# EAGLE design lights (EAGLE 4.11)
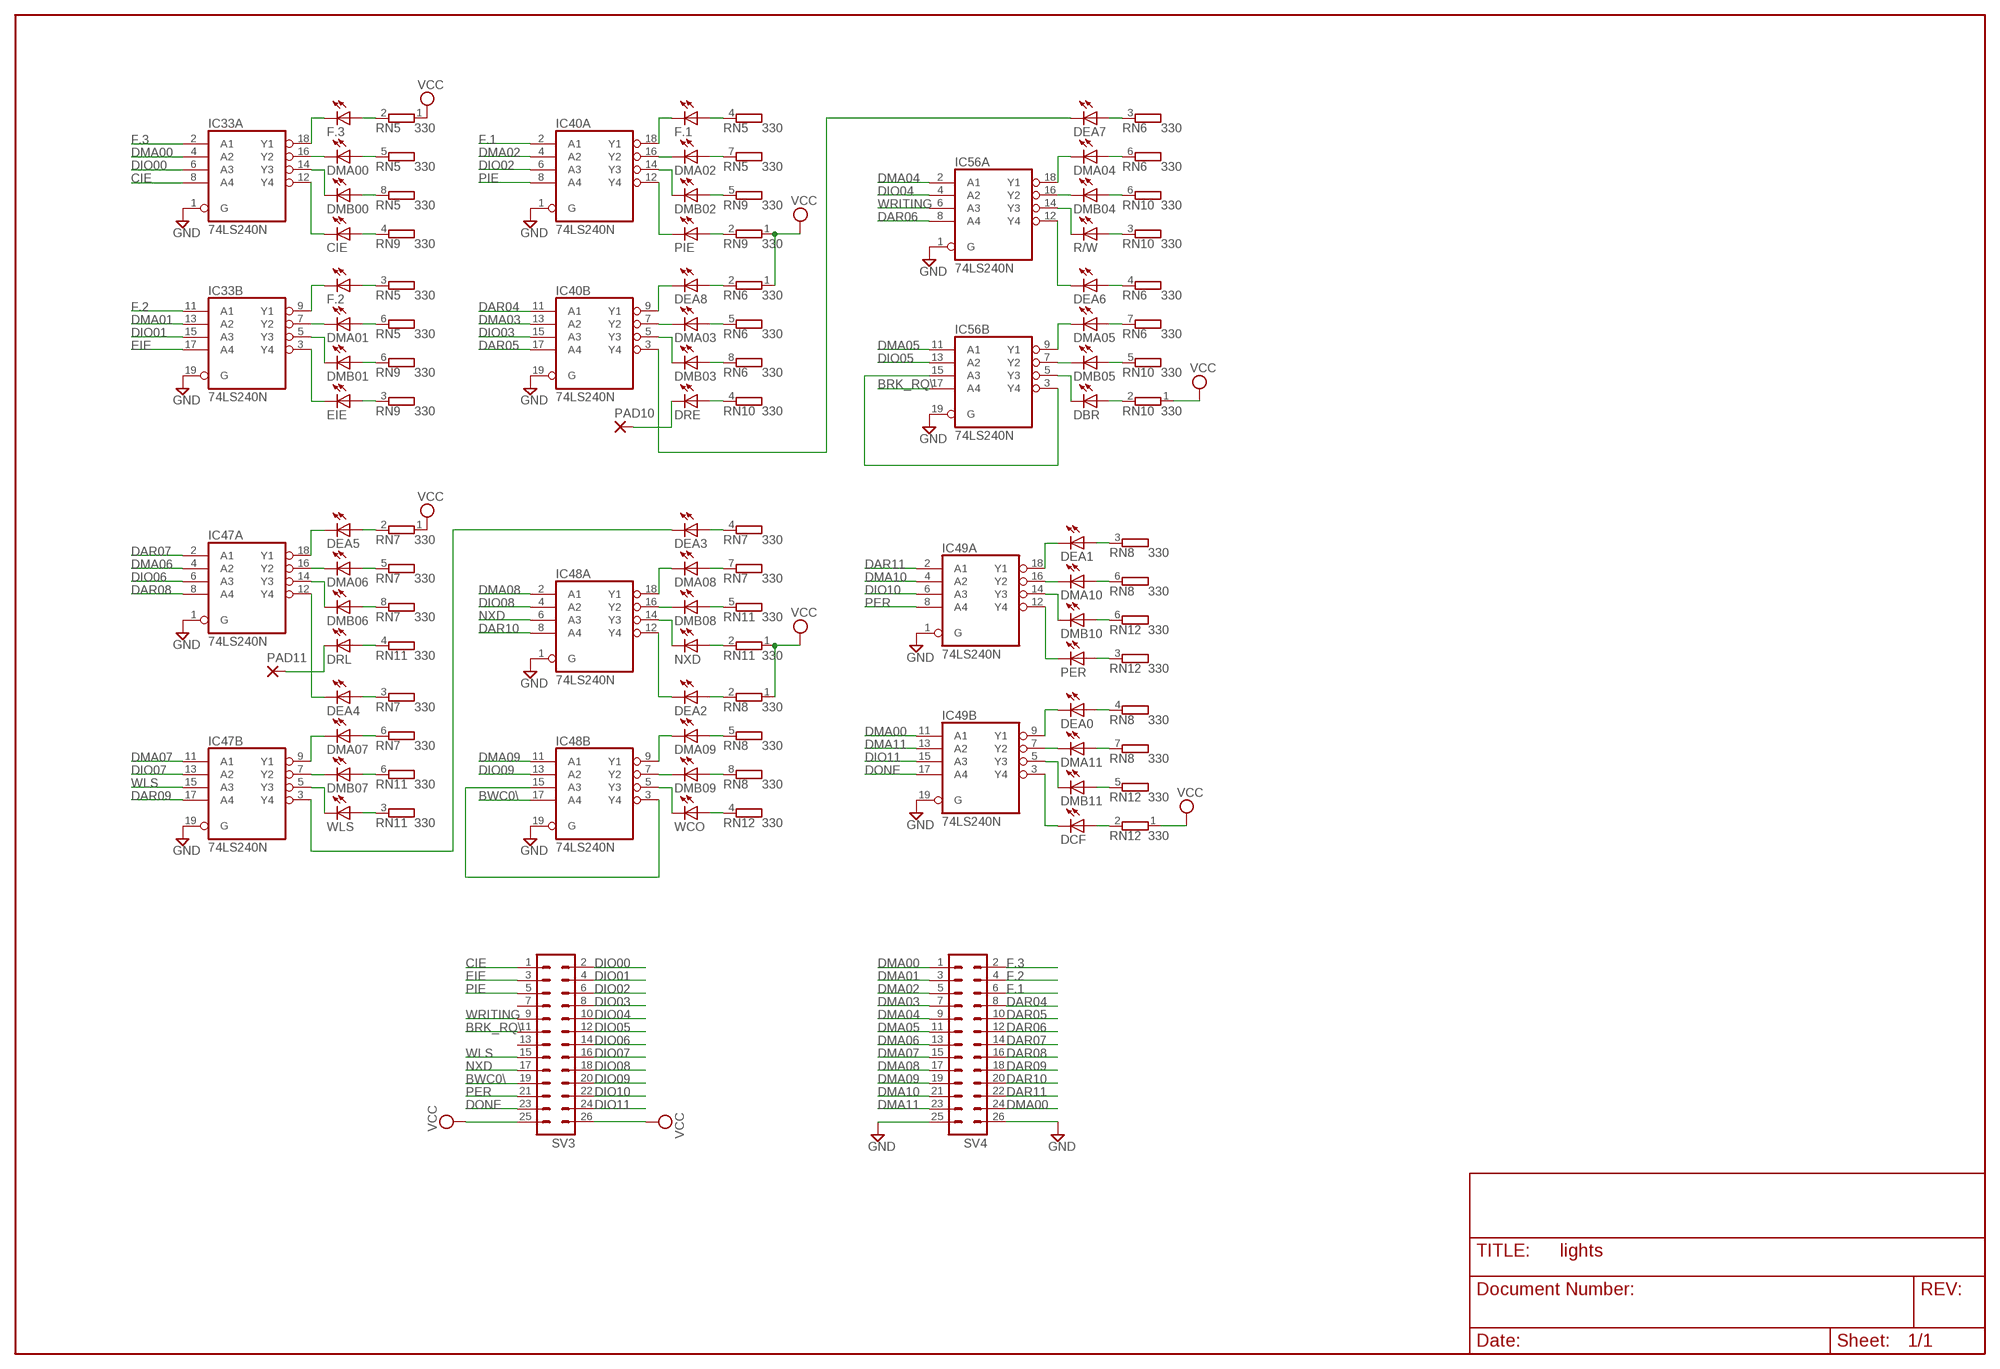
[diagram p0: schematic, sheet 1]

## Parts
CIE  LED5MM  [LED5MM]
DBR  LED5MM  [LED5MM]
DCF  LED5MM  [LED5MM]
DEA0  LED5MM  [LED5MM]
DEA1  LED5MM  [LED5MM]
DEA2  LED5MM  [LED5MM]
DEA3  LED5MM  [LED5MM]
DEA4  LED5MM  [LED5MM]
DEA5  LED5MM  [LED5MM]
DEA6  LED5MM  [LED5MM]
DEA7  LED5MM  [LED5MM]
DEA8  LED5MM  [LED5MM]
DMA00  LED5MM  [LED5MM]
DMA01  LED5MM  [LED5MM]
DMA02  LED5MM  [LED5MM]
DMA03  LED5MM  [LED5MM]
DMA04  LED5MM  [LED5MM]
DMA05  LED5MM  [LED5MM]
DMA06  LED5MM  [LED5MM]
DMA07  LED5MM  [LED5MM]
DMA08  LED5MM  [LED5MM]
DMA09  LED5MM  [LED5MM]
DMA10  LED5MM  [LED5MM]
DMA11  LED5MM  [LED5MM]
DMB00  LED5MM  [LED5MM]
DMB01  LED5MM  [LED5MM]
DMB02  LED5MM  [LED5MM]
DMB03  LED5MM  [LED5MM]
DMB04  LED5MM  [LED5MM]
DMB05  LED5MM  [LED5MM]
DMB06  LED5MM  [LED5MM]
DMB07  LED5MM  [LED5MM]
DMB08  LED5MM  [LED5MM]
DMB09  LED5MM  [LED5MM]
DMB10  LED5MM  [LED5MM]
DMB11  LED5MM  [LED5MM]
DRE  LED5MM  [LED5MM]
DRL  LED5MM  [LED5MM]
EIE  LED5MM  [LED5MM]
F.1  LED5MM  [LED5MM]
F.2  LED5MM  [LED5MM]
F.3  LED5MM  [LED5MM]
IC33  74LS240N  [DIL20]
IC40  74LS240N  [DIL20]
IC47  74LS240N  [DIL20]
IC48  74LS240N  [DIL20]
IC49  74LS240N  [DIL20]
IC56  74LS240N  [DIL20]
NXD  LED5MM  [LED5MM]
PAD10  1,6/0,8  [1,6/0,8]
PAD11  1,6/0,8  [1,6/0,8]
PER  LED5MM  [LED5MM]
PIE  LED5MM  [LED5MM]
R/W  LED5MM  [LED5MM]
RN5  330  GE07RP  [SIL8]
RN6  330  GE07RP  [SIL8]
RN7  330  GE07RP  [SIL8]
RN8  330  GE07RP  [SIL8]
RN9  330  GE05RP  [SIL6]
RN10  330  GE05RP  [SIL6]
RN11  330  GE05RP  [SIL6]
RN12  330  GE05RP  [SIL6]
SV3  MA13-2  [MA13-2]
SV4  MA13-2  [MA13-2]
WCO  LED5MM  [LED5MM]
WLS  LED5MM  [LED5MM]

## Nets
BRK_RQ\: IC56.17(B:A4) SV3.11
BWC0\: IC48.17(B:A4) SV3.19
CIE: IC33.8(A:A4) SV3.1
DAR04: IC40.11(B:A1) SV4.8
DAR05: IC40.17(B:A4) SV4.10
DAR06: IC56.8(A:A4) SV4.12
DAR07: IC47.2(A:A1) SV4.14
DAR08: IC47.8(A:A4) SV4.16
DAR09: IC47.17(B:A4) SV4.18
DAR10: IC48.8(A:A4) SV4.20
DAR11: IC49.2(A:A1) SV4.22
DIO00: IC33.6(A:A3) SV3.2
DIO01: IC33.15(B:A3) SV3.4
DIO02: IC40.6(A:A3) SV3.6
DIO03: IC40.15(B:A3) SV3.8
DIO04: IC56.4(A:A2) SV3.10
DIO05: IC56.13(B:A2) SV3.12
DIO06: IC47.6(A:A3) SV3.14
DIO07: IC47.13(B:A2) SV3.16
DIO08: IC48.4(A:A2) SV3.18
DIO09: IC48.13(B:A2) SV3.20
DIO10: IC49.6(A:A3) SV3.22
DIO11: IC49.15(B:A3) SV3.24
DMA00: IC33.4(A:A2) IC49.11(B:A1) SV4.1 SV4.24
DMA01: IC33.13(B:A2) SV4.3
DMA02: IC40.4(A:A2) SV4.5
DMA03: IC40.13(B:A2) SV4.7
DMA04: IC56.2(A:A1) SV4.9
DMA05: IC56.11(B:A1) SV4.11
DMA06: IC47.4(A:A2) SV4.13
DMA07: IC47.11(B:A1) SV4.15
DMA08: IC48.2(A:A1) SV4.17
DMA09: IC48.11(B:A1) SV4.19
DMA10: IC49.4(A:A2) SV4.21
DMA11: IC49.13(B:A2) SV4.23
DONE: IC49.17(B:A4) SV3.23
EIE: IC33.17(B:A4) SV3.3
F.1: IC40.2(A:A1) SV4.6
F.2: IC33.11(B:A1) SV4.4
F.3: IC33.2(A:A1) SV4.2
GND: IC33.1(A:G) IC33.19(B:G) IC40.1(A:G) IC40.19(B:G) IC47.1(A:G) IC47.19(B:G) IC48.1(A:G) IC48.19(B:G) IC49.1(A:G) IC49.19(B:G) IC56.1(A:G) IC56.19(B:G) SV4.25 SV4.26
N$42: F.3.A RN5.2
N$43: F.2.A RN5.3
N$44: F.1.A RN5.4
N$45: DEA8.A RN6.2
N$46: DEA2.A RN8.2
N$47: DEA1.A RN8.3
N$48: DEA5.A RN7.2
N$49: DEA4.A RN7.3
N$50: DEA3.A RN7.4
N$51: DEA0.A RN8.4
N$52: DMA09.A RN8.5
N$85: DMA10.A RN8.6
N$86: DMA00.A RN5.5
N$87: DMA01.A RN5.6
N$88: DMA02.A RN5.7
N$89: DEA7.A RN6.3
N$90: DEA6.A RN6.4
N$91: DMA03.A RN6.5
N$92: DMA07.A RN7.6
N$93: DMA06.A RN7.5
N$94: DMA08.A RN7.7
N$95: DMA11.A RN8.7
N$96: DMB09.A RN8.8
N$97: DMB10.A RN12.6
N$98: PIE.A RN9.2
N$99: EIE.A RN9.3
N$100: CIE.A RN9.4
N$101: DMA04.A RN6.6
N$102: DMA05.A RN6.7
N$103: DMB03.A RN6.8
N$104: DMB06.A RN7.8
N$105: DMB07.A RN11.6
N$106: DMB08.A RN11.5
N$107: DMB11.A RN12.5
N$108: RN12.4 WCO.A
N$109: PER.A RN12.3
N$110: DMB02.A RN9.5
N$111: DMB01.A RN9.6
N$112: DMB00.A RN5.8
N$113: DRE.A RN10.4
N$114: R/W.A RN10.3
N$115: DBR.A RN10.2
N$116: DRL.A RN11.4
N$117: RN11.3 WLS.A
N$118: NXD.A RN11.2
N$119: DCF.A RN12.2
N$120: DMA09.K(C) IC48.9(B:Y1)
N$121: DMB09.K(C) IC48.7(B:Y2)
N$122: F.3.K(C) IC33.18(A:Y1)
N$123: DMA00.K(C) IC33.16(A:Y2)
N$124: CIE.K(C) IC33.12(A:Y4)
N$125: DMB00.K(C) IC33.14(A:Y3)
N$126: DMA01.K(C) IC33.7(B:Y2)
N$127: F.2.K(C) IC33.9(B:Y1)
N$128: DMB01.K(C) IC33.5(B:Y3)
N$129: EIE.K(C) IC33.3(B:Y4)
N$132: F.1.K(C) IC40.18(A:Y1)
N$133: DMA02.K(C) IC40.16(A:Y2)
N$134: DMB02.K(C) IC40.14(A:Y3)
N$135: IC40.12(A:Y4) PIE.K(C)
N$136: DMB03.K(C) IC40.5(B:Y3)
N$137: DMA03.K(C) IC40.7(B:Y2)
N$138: DEA8.K(C) IC40.9(B:Y1)
N$139: DEA7.K(C) IC40.3(B:Y4)
N$140: DMA04.K(C) IC56.18(A:Y1)
N$141: DMB04.K(C) IC56.16(A:Y2)
N$142: IC56.14(A:Y3) R/W.K(C)
N$143: DMB05.K(C) IC56.7(B:Y2)
N$144: DEA6.K(C) IC56.12(A:Y4)
N$145: DBR.K(C) IC56.5(B:Y3)
N$146: DMA06.K(C) IC47.16(A:Y2)
N$147: DEA4.K(C) IC47.12(A:Y4)
N$148: DMB07.K(C) IC47.7(B:Y2)
N$149: DEA5.K(C) IC47.18(A:Y1)
N$150: DMA07.K(C) IC47.9(B:Y1)
N$151: IC47.5(B:Y3) WLS.K(C)
N$152: DMB06.K(C) IC47.14(A:Y3)
N$153: DEA3.K(C) IC47.3(B:Y4)
N$154: DMA08.K(C) IC48.18(A:Y1)
N$155: DMB08.K(C) IC48.16(A:Y2)
N$156: IC48.14(A:Y3) NXD.K(C)
N$157: IC48.5(B:Y3) WCO.K(C)
N$158: IC49.12(A:Y4) PER.K(C)
N$159: DMB10.K(C) IC49.14(A:Y3)
N$160: DEA2.K(C) IC48.12(A:Y4)
N$161: DMA10.K(C) IC49.16(A:Y2)
N$162: DEA1.K(C) IC49.18(A:Y1)
N$163: IC48.3(B:Y4) IC48.15(B:A3)
N$164: DMA11.K(C) IC49.7(B:Y2)
N$165: DEA0.K(C) IC49.9(B:Y1)
N$166: DMB11.K(C) IC49.5(B:Y3)
N$167: DCF.K(C) IC49.3(B:Y4)
N$169: DRE.K(C) PAD10.1(P)
N$170: DRL.K(C) PAD11.1(P)
N$171: DMA05.K(C) IC56.9(B:Y1)
N$172: DMB04.A RN10.6
N$173: DMB05.A RN10.5
N$175: IC56.3(B:Y4) IC56.15(B:A3)
NXD: IC48.6(A:A3) SV3.17
PER: IC49.8(A:A4) SV3.21
PIE: IC40.8(A:A4) SV3.5
VCC [Power]: RN5.1 RN6.1 RN7.1 RN8.1 RN9.1 RN10.1 RN11.1 RN12.1 SV3.25 SV3.26
WLS: IC47.15(B:A3) SV3.15
WRITING: IC56.6(A:A3) SV3.9
Unconnected: SV3.7 SV3.13

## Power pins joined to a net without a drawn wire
GND: IC33.10(P:GND) IC40.10(P:GND) IC47.10(P:GND) IC48.10(P:GND) IC49.10(P:GND) IC56.10(P:GND)
VCC: IC33.20(P:VCC) IC40.20(P:VCC) IC47.20(P:VCC) IC48.20(P:VCC) IC49.20(P:VCC) IC56.20(P:VCC)

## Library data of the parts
CIE DBR DCF DEA0 DEA1-DEA8 DMA00 DMA01-DMA09 DMA10 DMA11 DMB00 DMB01-DMB09 DMB10 DMB11 DRE DRL EIE F.1-F.3 NXD PER PIE R/W WCO WLS = led:LED: LED
IC33 IC40 IC47-IC49 IC56 = 74xx-jameco:74*240: Octal BUFFER and LINE DRIVER, 3-state
PAD10 PAD11 = wirepad:1,6/0,8: THROUGH-HOLE PAD
RN5-RN8 = resistor-sil:GE07RP: SIL RESISTOR
RN9-RN12 = resistor-sil:GE05RP: SIL RESISTOR
SV3 SV4 = con-lstb:MA13-2: PIN HEADER

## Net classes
1 Power: width 0.508 mm

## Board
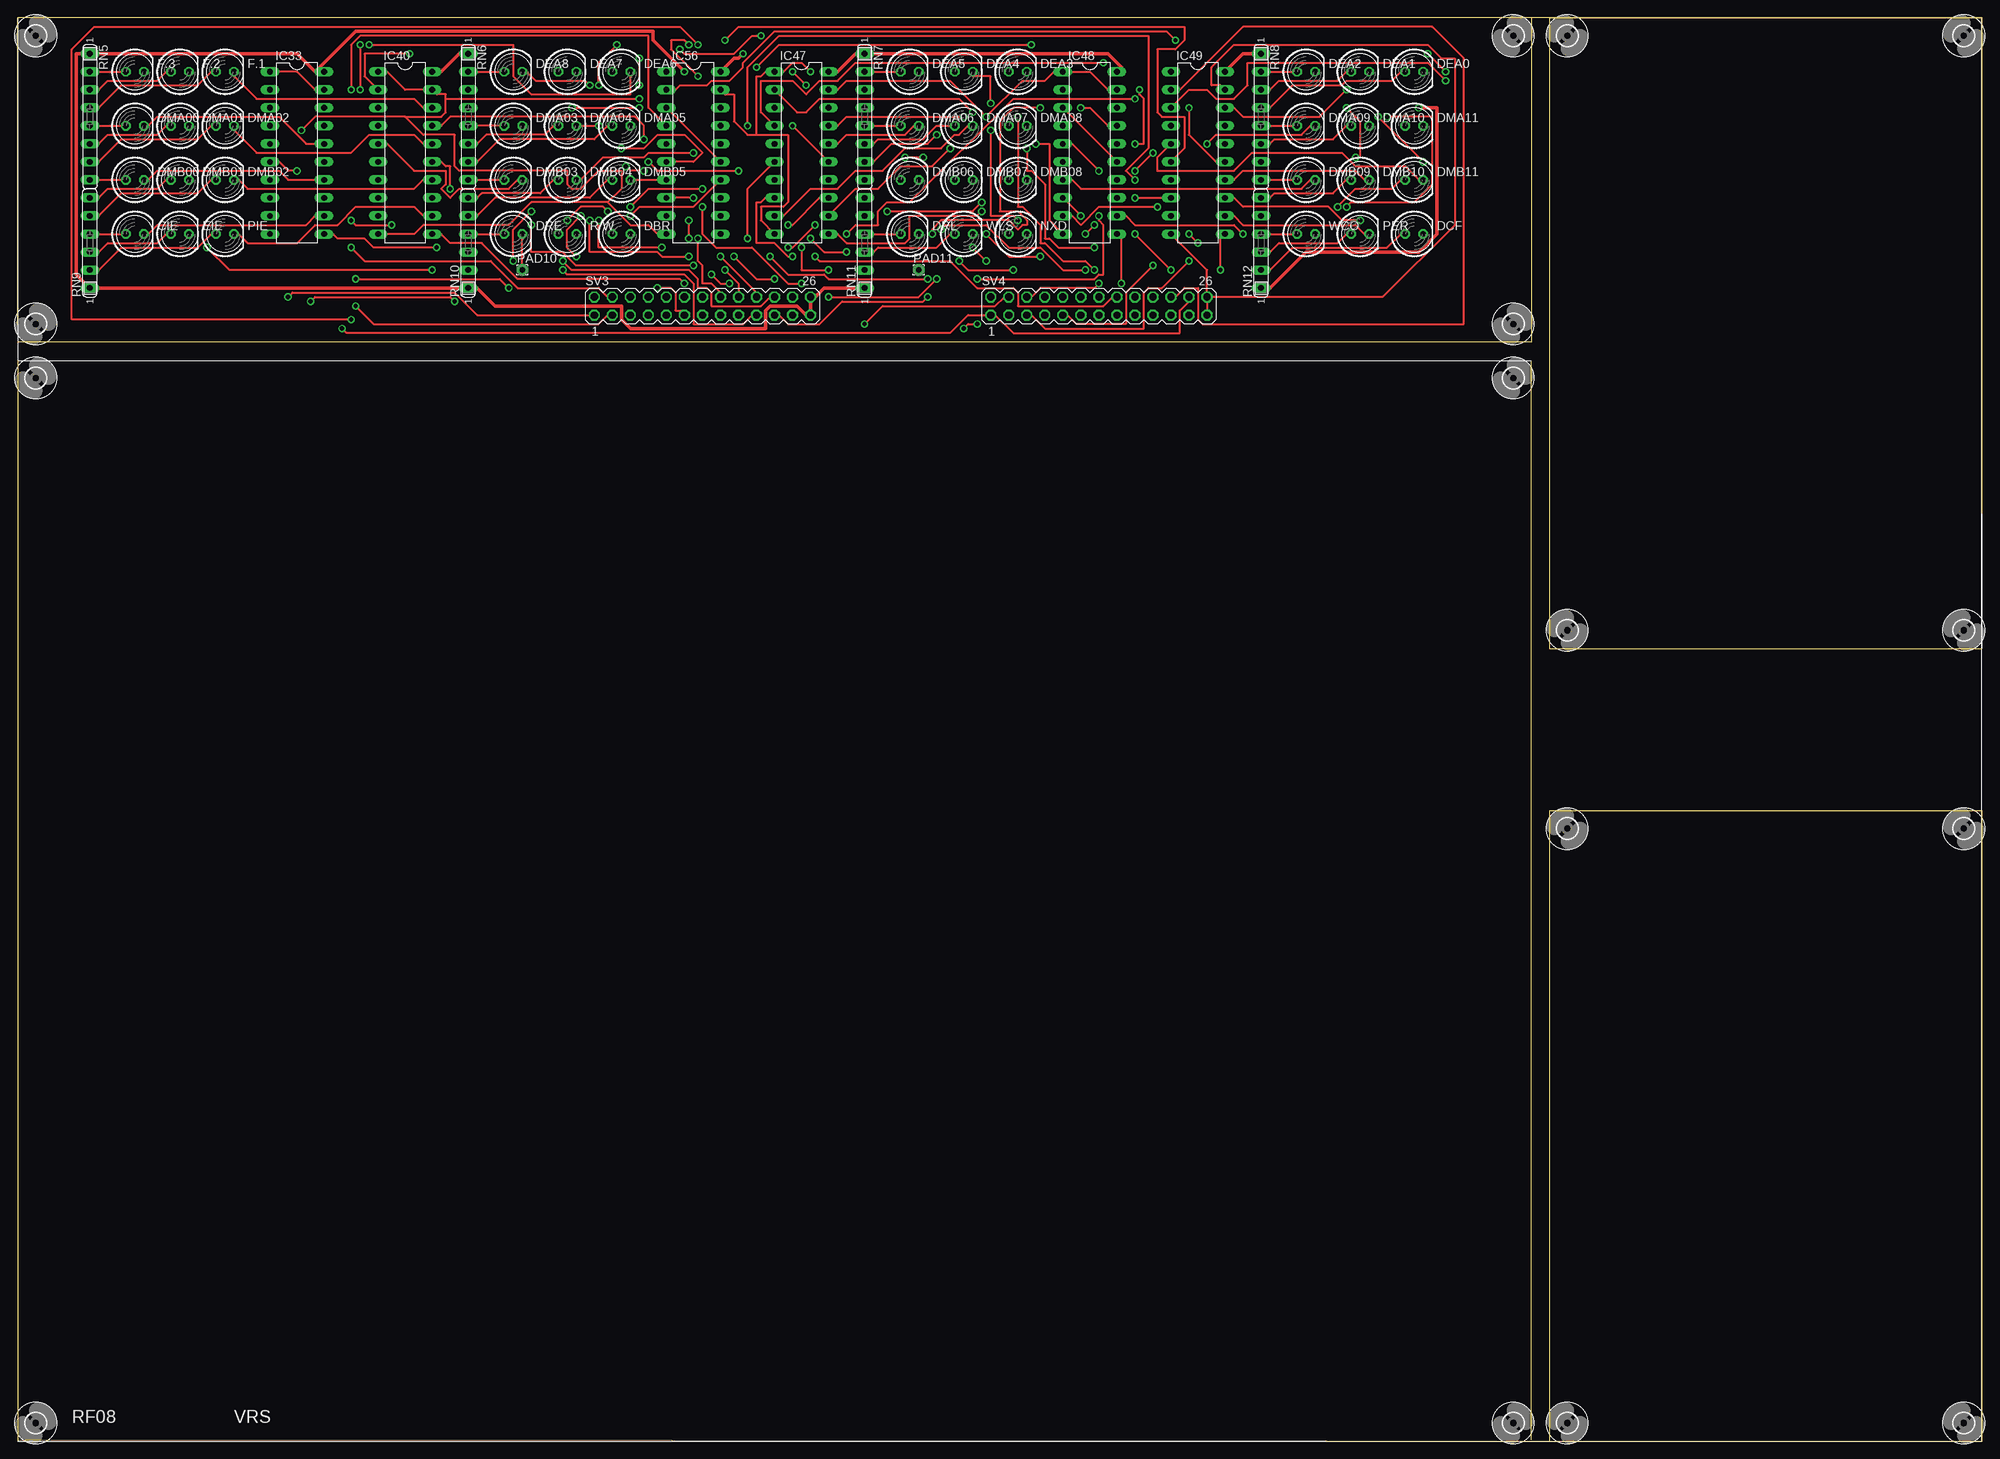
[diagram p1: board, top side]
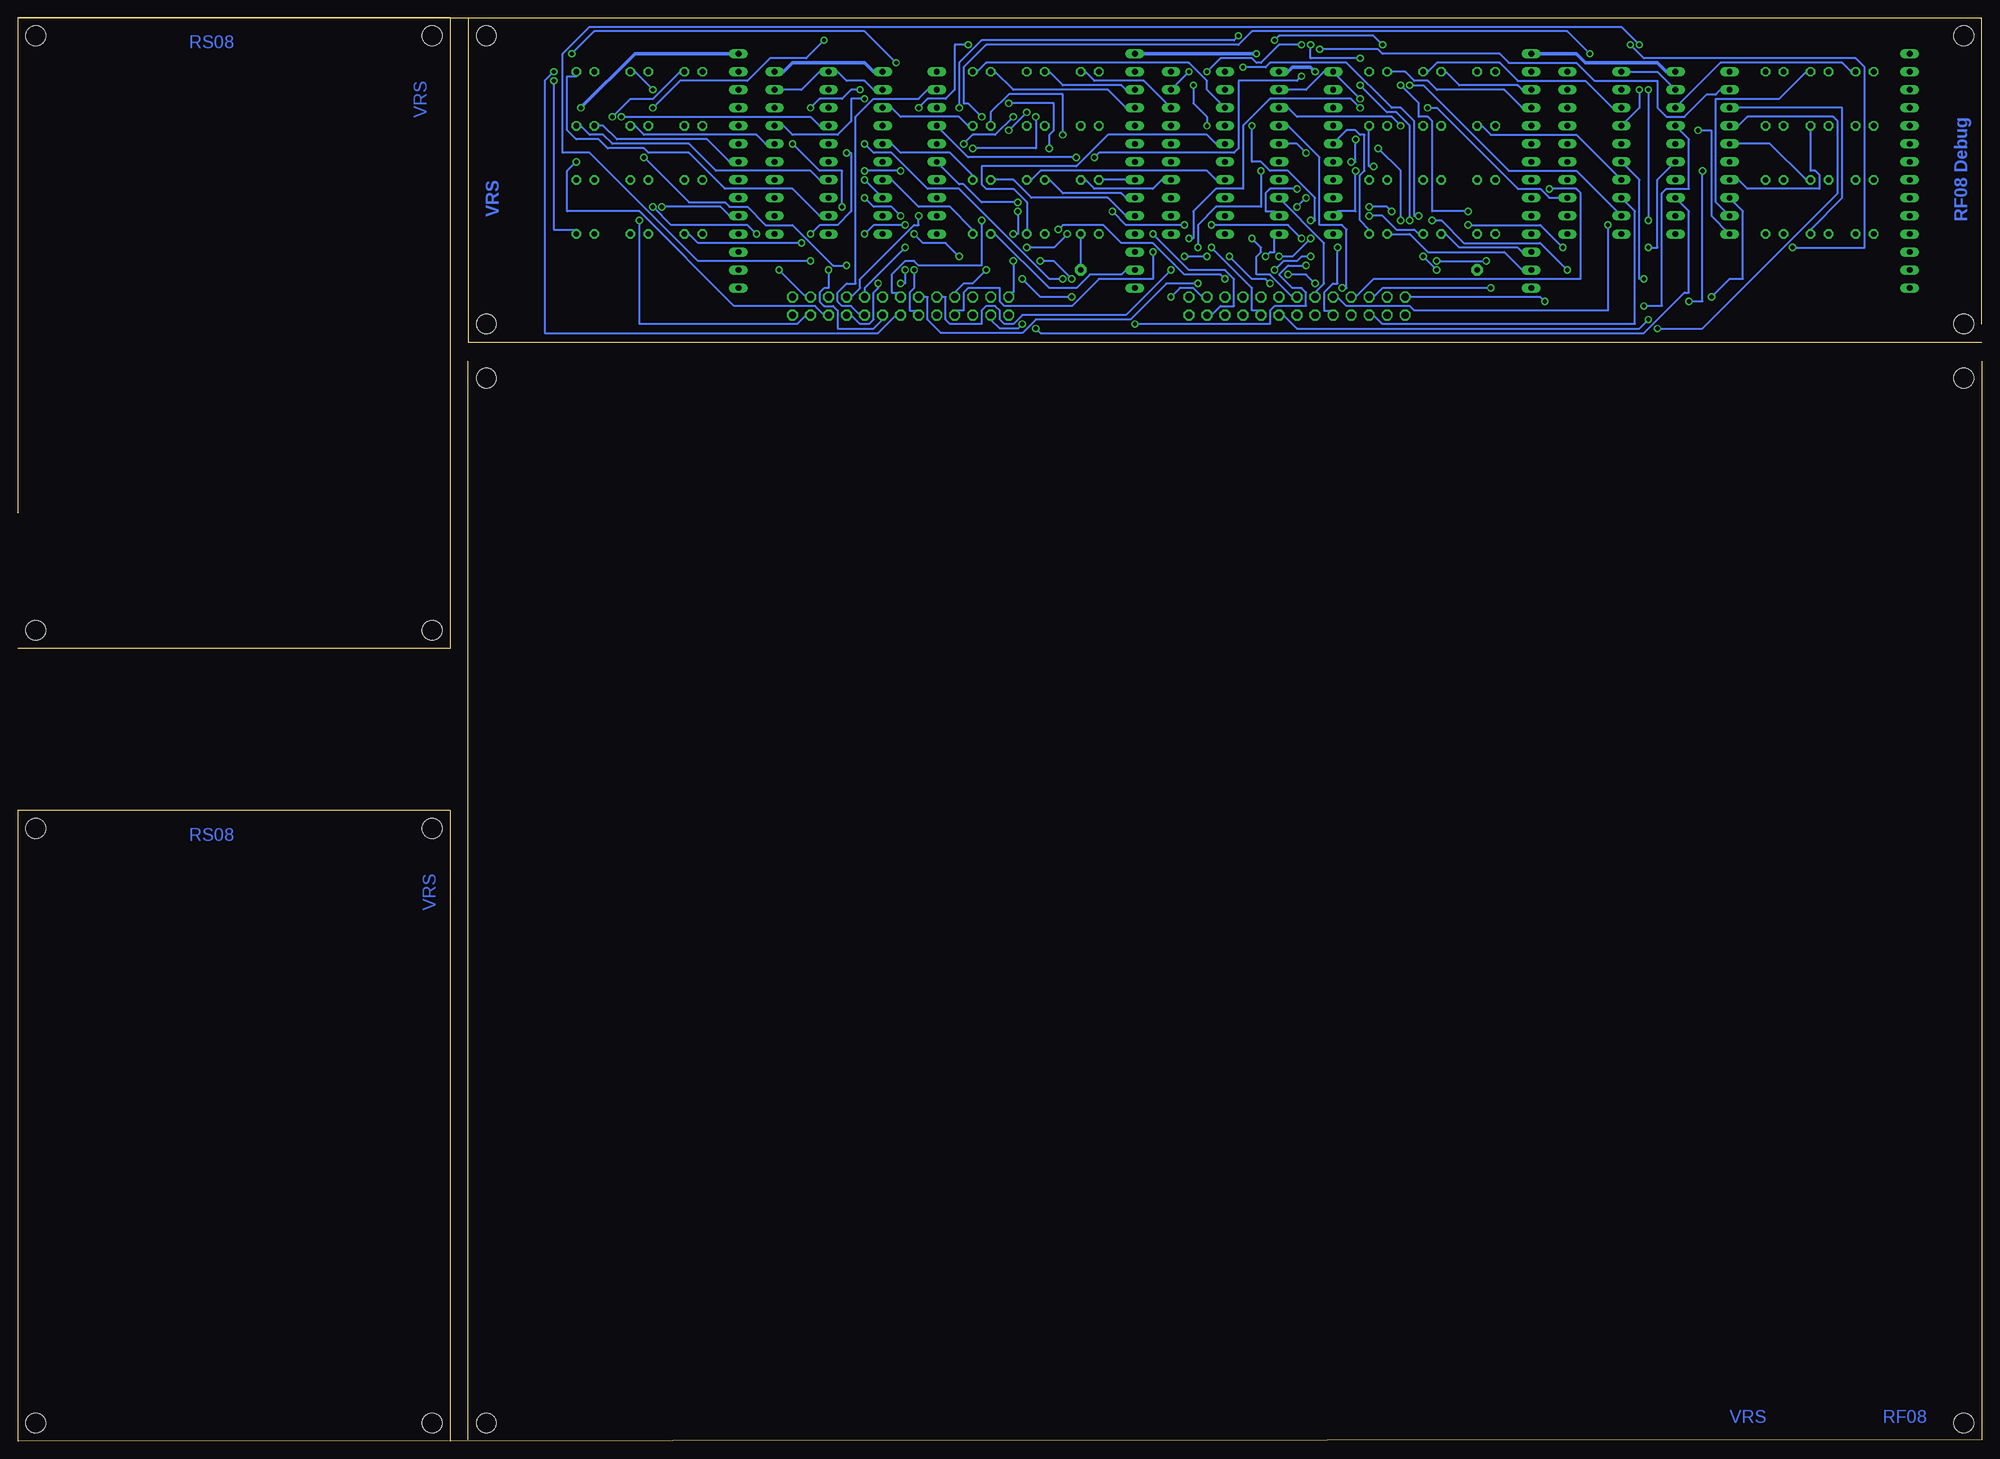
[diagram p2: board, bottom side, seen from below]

Size 276.86 x 200.67 mm. Coordinates in mm from the lower left corner, seen from the top.
Outline: 276.69,0 0.01,0.18 0.01,152.25
Outline: 213.34,0.18 213.34,152.25
Outline: 215.9,0.01 215.9,88.92 276.86,88.92 276.86,0.01
Outline: 276.86,111.78 215.9,111.78 215.9,200.67 276.86,200.67
Outline: 276.86,200.67 0,200.67 0,157.49
Outline: 276.86,200.67 276.86,130.82
Outline: 0,154.95 213.36,154.95 213.36,200.67
Copper layers (1*16): Top 0.035mm / dielectric 1.5mm / Bottom 0.035mm
Design rules "olimex10mil": minimum track width 10mil, minimum drill 24mil, track to track 10mil, track to pad 10mil, pad to pad 10mil, via to via 10mil, smd to smd 10mil, copper to edge 40mil, drill to drill 10mil, minimum pad ring 10mil, minimum via ring 8mil, stop-mask expansion 0mil, vias tented up to drill 0mil, thermal gap 10mil

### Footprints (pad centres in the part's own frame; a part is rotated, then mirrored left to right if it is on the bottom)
LED5MM = drill 0.813 octagon: A -1.27,0; K 1.27,0
DIL20 = drill 0.813 long: 1 -11.43,-3.81; 2 -8.89,-3.81; 3 -6.35,-3.81; 4 -3.81,-3.81; 5 -1.27,-3.81; 6 1.27,-3.81; 7 3.81,-3.81; 8 6.35,-3.81; 9 8.89,-3.81; 10 11.43,-3.81; 11 11.43,3.81; 12 8.89,3.81; 13 6.35,3.81; 14 3.81,3.81; 15 1.27,3.81; 16 -1.27,3.81; 17 -3.81,3.81; 18 -6.35,3.81; 19 -8.89,3.81; 20 -11.43,3.81
1,6/0,8 = drill 0.813 pad 1.6 octagon: 1 0,0
SIL8 = drill 0.813 long: 1 -8.89,0; 2 -6.35,0; 3 -3.81,0; 4 -1.27,0; 5 1.27,0; 6 3.81,0; 7 6.35,0; 8 8.89,0
SIL6 = drill 0.813 long: 1 -6.35,0; 2 -3.81,0; 3 -1.27,0; 4 1.27,0; 5 3.81,0; 6 6.35,0
MA13-2 = drill 1.016 octagon: 1 -15.24,-1.27; 2 -15.24,1.27; 3 -12.7,-1.27; 4 -12.7,1.27; 5 -10.16,-1.27; 6 -10.16,1.27; 7 -7.62,-1.27; 8 -7.62,1.27; 9 -5.08,-1.27; 10 -5.08,1.27; 11 -2.54,-1.27; 12 -2.54,1.27; 13 0,-1.27; 14 0,1.27; 15 2.54,-1.27; 16 2.54,1.27; 17 5.08,-1.27; 18 5.08,1.27; 19 7.62,-1.27; 20 7.62,1.27; 21 10.16,-1.27; 22 10.16,1.27; 23 12.7,-1.27; 24 12.7,1.27; 25 15.24,-1.27; 26 15.24,1.27
2,8 = hole 2.8: 0,0

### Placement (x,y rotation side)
CIE  16.51,170.19 0 top
DBR  85.09,170.19 0 top
DCF  196.85,170.19 0 top
DEA0  196.85,193.05 0 top
DEA1  189.23,193.05 0 top
DEA2  181.61,193.05 0 top
DEA3  140.97,193.05 0 top
DEA4  133.35,193.05 0 top
DEA5  125.73,193.05 0 top
DEA6  85.09,193.05 0 top
DEA7  77.47,193.05 0 top
DEA8  69.85,193.05 0 top
DMA00  16.51,185.43 0 top
DMA01  22.86,185.43 0 top
DMA02  29.21,185.43 0 top
DMA03  69.85,185.43 0 top
DMA04  77.47,185.43 0 top
DMA05  85.09,185.43 0 top
DMA06  125.73,185.43 0 top
DMA07  133.35,185.43 0 top
DMA08  140.97,185.43 0 top
DMA09  181.61,185.43 0 top
DMA10  189.23,185.43 0 top
DMA11  196.85,185.43 0 top
DMB00  16.51,177.81 0 top
DMB01  22.86,177.81 0 top
DMB02  29.21,177.81 0 top
DMB03  69.85,177.81 0 top
DMB04  77.47,177.81 0 top
DMB05  85.09,177.81 0 top
DMB06  125.73,177.81 0 top
DMB07  133.35,177.81 0 top
DMB08  140.97,177.81 0 top
DMB09  181.61,177.81 0 top
DMB10  189.23,177.81 0 top
DMB11  196.85,177.81 0 top
DRE  69.85,170.19 0 top
DRL  125.73,170.19 0 top
EIE  22.86,170.19 0 top
F.1  29.21,193.05 0 top
F.2  22.86,193.05 0 top
F.3  16.51,193.05 0 top
IC33  39.37,181.62 270 top
IC40  54.61,181.62 270 top
IC47  110.49,181.62 270 top
IC48  151.13,181.62 270 top
IC49  166.37,181.62 270 top
IC56  95.25,181.62 270 top
NXD  140.97,170.19 0 top
PAD10  71.12,165.11 0 top
PAD11  127,165.11 0 top
PER  189.23,170.19 0 top
PIE  29.21,170.19 0 top
R/W  77.47,170.19 0 top
RN5  10.16,186.7 270 top
RN6  63.5,186.7 270 top
RN7  119.38,186.7 270 top
RN8  175.26,186.7 270 top
RN9  10.16,168.92 90 top
RN10  63.5,168.92 90 top
RN11  119.38,168.92 90 top
RN12  175.26,168.92 90 top
SV3  96.52,160.03 0 top
SV4  152.4,160.03 0 top
U$1  [2,8]  2.54,149.88 0 top
U$2  [2,8]  210.82,149.88 0 top
U$3  [2,8]  2.54,2.56 0 top
U$4  [2,8]  210.82,2.56 0 top
U$5  [2,8]  274.32,2.56 90 top
U$6  [2,8]  218.44,2.56 90 top
U$7  [2,8]  218.44,86.38 90 top
U$8  [2,8]  274.32,86.38 90 top
U$9  [2,8]  274.32,198.13 90 top
U$10  [2,8]  274.32,114.31 90 top
U$11  [2,8]  218.44,114.31 90 top
U$12  [2,8]  218.44,198.13 90 top
U$13  [2,8]  2.54,157.49 0 top
U$14  [2,8]  2.54,198.13 0 top
U$16  [2,8]  210.82,157.49 0 top
U$17  [2,8]  210.82,198.13 0 top
U$18  [SIERRA-PROTO]  0,0.01 0 top
WCO  181.61,170.19 0 top
WLS  133.35,170.19 0 top

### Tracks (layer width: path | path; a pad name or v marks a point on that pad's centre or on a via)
BRK_RQ\  (via drill 0.61)
  Top 0.254: v90.17,162.57 92.08,162.57 92.71,161.94 92.71,159.4 93.98,159.4 SV3.11
  Bottom 0.254: v90.17,162.57 89.53,162.57 89.53,170.83 90.17,171.46 93.34,171.46 93.34,180.99 97.79,185.43 IC56.17
BWC0\  (via drill 0.61)
  Top 0.254: v149.86,187.97 151.13,187.97 153.67,185.43 IC48.17 | v142.88,196.86 107.31,196.86 v104.14,193.69 | v79.38,172.73 77.47,170.83 77.47,168.29 v78.74,167.02 | v76.83,165.11 77.47,164.48 93.98,164.48 95.25,163.21 95.25,157.49 102.23,157.49 103.5,158.76 SV3.19
  Bottom 0.254: v149.86,187.97 148.59,189.24 146.05,189.24 144.78,190.51 144.78,196.86 v142.88,196.86 | v104.14,193.69 100.97,193.69 100.33,194.32 89.53,194.32 83.19,187.97 81.92,187.97 80.01,186.07 80.01,172.73 v79.38,172.73 | v76.83,165.11 v78.74,167.02
CIE  (via drill 0.61)
  Top 0.254: v38.1,161.3 38.73,161.94 61.59,161.94 64.77,158.76 SV3.1
  Bottom 0.254: v38.1,161.3 35.56,163.84 33.66,163.84 33.66,173.37 IC33.8
DAR04  (via drill 0.61)
  Top 0.254: v93.98,163.21 93.34,163.84 70.48,163.84 65.41,168.92 60.96,168.92 59.69,170.19 IC40.11 | v97.79,164.48 99.06,163.21 v100.33,163.21 | v106.05,167.02 108.58,164.48 113.67,164.48 114.3,163.84 v128.27,163.84 | v132.72,166.38 133.99,165.11 v140.34,165.11
  Bottom 0.254: v93.98,163.21 95.25,164.48 v97.79,164.48 | v100.33,163.21 100.97,163.84 102.87,163.84 v106.05,167.02 | v128.27,163.84 130.81,166.38 v132.72,166.38 | v140.34,165.11 142.24,163.21 143.51,163.21 144.78,161.94 SV4.8
DAR05  (via drill 0.61)
  Top 0.254: v88.27,183.53 88.27,185.43 87,186.7 60.96,186.7 59.69,185.43 IC40.17 | v88.9,180.35 90.17,179.08 v101.6,179.08 | v110.49,168.29 110.49,165.11 v114.3,165.11
  Bottom 0.254: v88.27,183.53 88.27,180.35 v88.9,180.35 | v101.6,179.08 101.6,174 107.95,174 110.49,171.46 v110.49,168.29 | v114.3,165.11 120.65,158.76 135.25,158.76 136.53,157.49 137.79,157.49 138.43,158.13 138.43,159.4 139.06,160.03 140.34,160.03 140.97,159.4 140.97,157.49 145.41,157.49 146.05,158.13 146.05,161.3 SV4.10
DAR06  (via drill 0.61)
  Top 0.254: v96.52,174 96.52,170.19 98.42,168.29 103.5,168.29 108.58,163.21 v110.49,163.21 | v95.25,175.27 IC56.8
  Bottom 0.254: v96.52,174 v95.25,175.27 | v110.49,163.21 114.94,163.21 120.02,158.13 133.35,158.13 135.25,156.22 146.69,156.22 148.59,158.13 148.59,161.3 SV4.12
DAR07  (via drill 0.61)
  Top 0.254: v134.62,187.34 132.72,189.24 113.03,189.24 111.12,187.34 109.86,187.34 IC47.2 | v137.16,184.8 137.16,172.73 140.34,172.73 v140.97,172.1
  Bottom 0.254: v134.62,187.34 v137.16,184.8 | v140.97,172.1 140.97,165.75 149.86,165.75 150.5,166.38 151.76,166.38 153.67,164.48 153.67,161.94 152.4,161.94 SV4.14
DAR08  (via drill 0.61)
  Top 0.254: v109.22,167.02 108.58,167.02 106.68,168.92 104.14,168.92 104.14,174.64 104.78,174.64 105.41,175.27 IC47.8 | v112.39,167.02 113.03,166.38 131.44,166.38 135.25,162.57 140.34,162.57 140.97,161.94 140.97,160.03 153.03,160.03 154.31,161.3 SV4.16
  Bottom 0.254: v109.22,167.02 v112.39,167.02
DAR09  (via drill 0.61)
  Top 0.254: v133.35,186.7 116.84,186.7 115.57,185.43 IC47.17 | v142.24,182.26 142.24,179.08 142.88,179.08 144.78,177.18 144.78,169.56 145.41,169.56 146.69,168.29 v151.76,168.29
  Bottom 0.254: v133.35,186.7 133.35,182.26 v142.24,182.26 | v151.76,168.29 157.48,162.57 SV4.18
DAR10  (via drill 0.61)
  Top 0.254: v149.86,172.73 IC48.8
  Bottom 0.254: v149.86,172.73 149.86,171.46 150.5,171.46 158.12,163.84 158.12,162.57 159.38,161.3 SV4.20
DAR11
  Top 0.254: IC49.2 163.83,190.51 172.72,199.4 199.39,199.4 203.84,194.96 203.84,157.49 167,157.49 166.37,158.13 166.37,162.57 164.47,162.57 163.19,161.3 SV4.22
DIO00  (via drill 0.61)
  Top 0.254: v39.37,179.08 38.1,179.08 36.83,180.35 IC33.6 | v41.27,160.67 41.91,161.3 60.96,161.3 v61.59,160.67
  Bottom 0.254: v39.37,179.08 39.37,160.67 v41.27,160.67 | v61.59,160.67 62.23,161.3 SV3.2
DIO01  (via drill 0.61)
  Top 0.254: v46.99,168.29 48.9,166.38 66.67,166.38 70.48,162.57 81.92,162.57 83.19,161.3 SV3.4
  Bottom 0.254: v46.99,168.29 45.72,168.29 45.72,177.81 IC33.15
DIO02  (via drill 0.61)
  Top 0.254: v47.62,163.84 67.94,163.84 v69.22,162.57
  Bottom 0.254: v47.62,163.84 48.26,163.84 48.26,177.81 IC40.6 | v69.22,162.57 84.45,162.57 85.72,161.3 SV3.6
DIO03  (via drill 0.61)
  Top 0.254: v60.96,176.54 60.96,179.72 60.33,179.72 59.69,180.35 IC40.15
  Bottom 0.254: v60.96,176.54 57.15,176.54 56.52,175.91 56.52,163.84 85.72,163.84 88.27,161.3 SV3.8
DIO04  (via drill 0.61)
  Top 0.254: v46.99,190.51 46.99,196.86 48.26,198.13 88.9,198.13 88.9,187.97 IC56.4 | v46.99,172.1 47.62,171.46 v52.7,171.46
  Bottom 0.254: v46.99,190.51 v46.99,172.1 | v52.7,171.46 52.7,159.4 80.01,159.4 80.64,160.03 89.53,160.03 90.81,161.3 SV3.10
DIO05
  Bottom 0.254: IC56.13 92.71,168.92 92.71,163.21 93.98,161.94 SV3.12
DIO06  (via drill 0.61)
  Top 0.254: v102.87,169.56 102.87,176.54 IC47.6
  Bottom 0.254: v102.87,169.56 101.6,168.29 101.6,167.65 102.23,167.02 102.23,164.48 100.33,164.48 97.16,161.3 SV3.14
DIO07  (via drill 0.61)
  Top 0.254: v108.58,171.46 109.22,171.46 113.03,175.27 IC47.13 | v95.89,169.56 95.89,166.38 96.52,165.75 96.52,163.21 97.79,163.21 99.06,161.94 SV3.16
  Bottom 0.254: v108.58,171.46 97.79,171.46 v95.89,169.56
DIO08  (via drill 0.61)
  Top 0.254: v125.09,180.99 v127.64,180.99 | v95.89,192.42 92.08,196.23 92.08,197.5 93.98,197.5 v94.61,196.86 | v87.63,191.15 v87.63,194.96 | v80.64,172.1 80.64,167.65 90.17,167.65 90.81,167.02 v94.61,167.02 | v99.69,165.11 101.6,163.21 SV3.18
  Bottom 0.254: v127.64,180.99 142.88,180.99 IC48.4 | v125.09,180.99 124.46,181.62 105.41,181.62 104.78,182.26 104.78,191.78 96.52,191.78 v95.89,192.42 | v94.61,196.86 94.61,194.96 v87.63,194.96 | v87.63,191.15 83.82,187.34 82.55,187.34 80.64,185.43 v80.64,172.1 | v94.61,167.02 95.89,167.02 96.52,166.38 98.42,166.38 v99.69,165.11
DIO09  (via drill 0.61)
  Top 0.254: v157.48,177.81 156.21,179.08 159.38,182.26 159.38,198.13 107.31,198.13 102.87,193.69 v102.87,185.43 | v94.61,169.56 v94.61,172.1 | v99.06,167.02 104.14,161.94 SV3.20
  Bottom 0.254: v102.87,185.43 102.87,180.35 101.6,180.35 100.33,179.08 97.79,179.08 93.98,175.27 93.98,172.1 v94.61,172.1 | v94.61,169.56 97.16,167.02 v99.06,167.02 | v157.48,177.81 IC48.13
DIO10  (via drill 0.61)
  Top 0.254: v99.69,197.5 101.6,199.4 164.47,199.4 164.47,197.5 163.19,196.23 160.66,196.23 160.66,187.34 161.29,186.7 164.47,186.7 164.47,182.26 IC49.6 | v84.45,196.86 81.92,194.32 v81.92,191.15 | v72.39,173.37 69.85,170.83 v69.85,166.38 | v76.83,166.38 78.11,165.11 94.61,165.11 95.89,163.84 95.89,162.57 97.16,162.57 97.79,161.94 97.79,160.03 104.78,160.03 106.05,161.3 SV3.22
  Bottom 0.254: v99.69,197.5 99.06,198.13 85.72,198.13 v84.45,196.86 | v81.92,191.15 79.38,188.61 79.38,186.7 78.11,186.7 77.47,186.07 77.47,173.37 v72.39,173.37 | v76.83,166.38 v69.85,166.38
DIO11  (via drill 0.61)
  Top 0.254: v165.1,187.97 165.1,184.16 168.91,180.35 IC49.15 | v158.12,190.51 158.12,189.88 158.75,189.24 158.75,182.89 v157.48,182.89 | v129.54,163.84 127,161.3 v114.3,161.3
  Bottom 0.254: v165.1,187.97 163.83,189.24 160.66,189.24 159.38,190.51 v158.12,190.51 | v157.48,182.89 156.21,181.62 153.67,181.62 148.59,176.54 144.15,176.54 131.44,163.84 v129.54,163.84 | v114.3,161.3 113.03,162.57 111.12,162.57 109.86,161.3 SV3.24
DMA00  (via drill 0.61)
  Top 0.254: v169.54,165.11 169.54,169.56 IC49.11 | v45.72,156.86 46.35,156.22 131.44,156.22 133.99,158.76 SV4.1 137.79,158.76 140.34,156.22 163.83,156.22 163.83,159.4 165.1,160.67 SV4.24
  Bottom 0.254: v169.54,165.11 165.74,161.3 SV4.24 | v45.72,156.86 39.37,156.86 20.32,175.91 20.32,186.07 20.95,186.7 33.02,186.7 34.29,185.43 IC33.4
DMA01  (via drill 0.61)
  Top 0.254: v133.35,156.86 133.99,157.49 v135.25,157.49
  Bottom 0.254: v133.35,156.86 132.72,156.22 47.62,156.22 41.91,161.94 41.27,161.94 41.27,173.37 IC33.13 | v135.25,157.49 135.89,156.86 138.43,156.86 139.7,158.13 SV4.3
DMA02  (via drill 0.61)
  Top 0.254: v48.26,196.86 v48.26,190.51 | v165.1,166.38 161.29,162.57 159.38,162.57 158.75,161.94 158.75,156.86 144.78,156.86 142.88,158.76 SV4.5
  Bottom 0.254: v48.26,190.51 48.26,187.97 IC40.4 | v48.26,196.86 50.8,199.4 196.22,199.4 200.03,195.59 200.03,181.62 196.22,181.62 180.97,166.38 v165.1,166.38
DMA03  (via drill 0.61)
  Top 0.254: v78.11,187.97 v87.63,187.97 | v111.76,169.56 113.67,167.65 v116.84,167.65
  Bottom 0.254: v78.11,187.97 76.83,187.97 65.41,176.54 62.23,176.54 60.96,175.27 IC40.13 | v87.63,187.97 88.9,189.24 100.33,189.24 104.14,185.43 104.14,176.54 107.95,176.54 111.12,173.37 111.12,169.56 v111.76,169.56 | v116.84,167.65 116.84,163.84 124.46,163.84 128.27,160.03 137.79,160.03 138.43,160.67 138.43,162.57 142.88,162.57 143.51,161.94 143.51,159.4 144.78,159.4 SV4.7
DMA04  (via drill 0.61)
  Top 0.254: v163.19,197.5 161.93,198.77 106.68,198.77 102.23,194.32 102.23,193.69 100.33,191.78 97.79,191.78 97.16,191.15 93.34,191.15 92.71,190.51 IC56.2 | v187.32,187.97 189.23,186.07 189.23,180.99 v188.59,180.99 | v160.02,165.75 156.21,161.94 156.21,157.49 149.22,157.49 147.96,158.76 SV4.9
  Bottom 0.254: v163.19,197.5 165.74,194.96 170.81,194.96 173.99,191.78 183.51,191.78 v187.32,187.97 | v188.59,180.99 182.25,174.64 177.16,174.64 176.53,174 173.99,174 171.45,171.46 167.64,171.46 161.93,165.75 v160.02,165.75
DMA05  (via drill 0.61)
  Top 0.254: v100.97,167.02 104.14,163.84 v106.68,163.84 | v130.18,170.83 130.81,171.46 136.53,171.46 139.7,168.29 144.15,168.29 147.32,165.11 v150.5,165.11
  Bottom 0.254: v100.97,167.02 100.33,167.65 99.69,167.65 99.69,169.56 IC56.11 | v106.68,163.84 107.31,164.48 112.39,164.48 116.84,168.92 121.28,168.92 123.83,171.46 129.54,171.46 v130.18,170.83 | v150.5,165.11 150.5,162.57 151.13,161.94 151.13,159.4 149.86,159.4 SV4.11
DMA06  (via drill 0.61)
  Top 0.254: v153.03,194.32 118.11,194.32 115.57,191.78 113.03,191.78 111.12,189.88 109.22,191.78 104.78,191.78 104.78,187.34 IC47.4 | v198.75,195.59 v201.29,193.05
  Bottom 0.254: v153.03,194.32 157.48,198.77 195.58,198.77 v198.75,195.59 | v201.29,193.05 202.56,191.78 202.56,156.22 155.57,156.22 153.03,158.76 SV4.13
DMA07  (via drill 0.61)
  Top 0.254: v135.89,173.37 135.25,172.73 125.73,172.73 125.73,169.56 125.09,168.92 116.84,168.92 115.57,170.19 IC47.11 | v136.53,170.19 139.7,167.02 v144.15,167.02 | v150.5,170.19 v151.76,171.46 | v157.48,170.19 v162.56,165.11
  Bottom 0.254: v135.89,173.37 135.89,170.19 v136.53,170.19 | v144.15,167.02 146.05,168.92 149.22,168.92 v150.5,170.19 | v151.76,171.46 156.21,171.46 v157.48,170.19 | v162.56,165.11 162.56,162.57 163.19,162.57 163.83,161.94 163.83,160.67 163.19,160.03 161.93,160.03 161.29,159.4 161.29,156.86 156.21,156.86 154.94,158.13 SV4.15
DMA08
  Bottom 0.254: IC48.2 148.59,190.51 149.86,189.24 156.21,189.24 158.75,186.7 158.75,163.21 160.02,163.21 161.29,161.94 161.29,160.67 160.66,160.03 159.38,160.03 158.12,158.76 SV4.17
DMA09  (via drill 0.61)
  Top 0.254: v155.57,163.21 155.57,169.56 IC48.11
  Bottom 0.254: v155.57,163.21 155.57,162.57 156.21,161.94 156.21,158.13 156.84,157.49 158.12,157.49 159.38,158.76 SV4.19
DMA10  (via drill 0.61)
  Top 0.254: v198.12,180.35 v191.77,186.7
  Bottom 0.254: v191.77,186.7 165.1,186.7 163.83,185.43 IC49.4 | v198.12,180.35 199.39,179.08 199.39,173.37 189.23,173.37 175.9,160.03 164.47,160.03 163.19,158.76 SV4.21
DMA11  (via drill 0.61)
  Top 0.254: v189.23,172.1 186.69,172.1 184.78,174 172.72,174 171.45,175.27 IC49.13
  Bottom 0.254: v189.23,172.1 189.23,157.49 167,157.49 165.74,158.76 SV4.23
DONE  (via drill 0.61)
  Top 0.254: v157.48,189.24 140.34,189.24 125.73,174.64 122.56,174.64 121.28,173.37 121.28,171.46 118.11,171.46 v116.84,170.19
  Bottom 0.254: v157.48,189.24 159.38,189.24 159.38,186.07 161.29,184.16 167.64,184.16 168.91,185.43 IC49.17 | v116.84,170.19 111.76,165.11 106.68,165.11 105.41,163.84 105.41,160.03 107.31,160.03 108.58,158.76 SV3.23
EIE  (via drill 0.61)
  Top 0.254: v47.62,160.03 50.16,157.49 81.92,157.49 83.19,158.76 SV3.3
  Bottom 0.254: v47.62,160.03 45.09,160.03 45.09,175.91 44.45,176.54 41.27,176.54 41.27,183.53 IC33.17
F.1  (via drill 0.61)
  Top 0.254: v55.24,195.59 48.9,195.59 48.9,192.42 IC40.2 | v140.97,186.7 140.97,174 141.6,174 144.15,171.46 144.15,168.92 144.78,168.92 147.32,166.38 150.5,166.38 v151.76,165.11 | v152.4,163.21 151.76,162.57 144.15,162.57 142.88,161.3 SV4.6
  Bottom 0.254: v55.24,195.59 58.42,198.77 102.87,198.77 104.78,196.86 140.34,196.86 143.51,193.69 143.51,188.61 142.88,188.61 v140.97,186.7 | v151.76,165.11 151.76,163.21 v152.4,163.21
F.2  (via drill 0.61)
  Top 0.254: v59.05,168.29 50.16,168.29 48.9,169.56 45.09,169.56 44.45,170.19 IC33.11 | v72.39,171.46 72.39,167.65 76.83,167.65 78.74,165.75 v95.25,165.75 | v119.38,157.49 121.92,160.03 137.79,160.03 139.06,161.3 SV4.4
  Bottom 0.254: v59.05,168.29 62.23,171.46 v72.39,171.46 | v95.25,165.75 97.79,165.75 99.06,164.48 97.16,162.57 95.89,162.57 95.25,161.94 95.25,160.03 99.69,160.03 100.33,159.4 100.33,157.49 v119.38,157.49
F.3  (via drill 0.61)
  Top 0.254: v93.34,196.23 93.98,195.59 100.97,195.59 103.5,198.13 v104.78,198.13 | v144.15,187.97 140.34,187.97 138.43,186.07 138.43,173.37 140.97,173.37 142.24,172.1 142.24,171.46 141.6,171.46 140.97,170.83 139.7,172.1 130.18,172.1 128.91,170.83 v128.91,170.19 | v134.62,168.29 v136.53,166.38
  Bottom 0.254: v93.34,196.23 85.09,196.23 84.45,195.59 67.94,195.59 66.67,194.32 57.15,194.32 54.61,191.78 45.72,191.78 45.72,187.97 44.45,186.7 41.91,186.7 38.73,189.88 37.47,189.88 36.83,190.51 IC33.2 | v104.78,198.13 105.41,197.5 140.97,197.5 144.15,194.32 v144.15,187.97 | v128.91,170.19 130.81,168.29 v134.62,168.29 | v136.53,166.38 136.53,161.94 137.16,161.94 SV4.2
GND  (via drill 0.61)
  Top 0.254: 83.19,174.64 72.39,174.64 69.22,171.46 57.15,171.46 55.88,170.19 IC40.10 | 83.19,174.64 86.36,171.46 88.9,171.46 90.17,170.19 IC56.10 | IC33.19 41.91,190.51 39.37,193.05 IC33.1 | v40.01,184.8 41.91,186.7 54.61,186.7 | 54.61,186.7 59.69,186.7 60.33,187.34 60.33,189.24 | 60.33,189.24 60.33,189.88 59.05,189.88 IC40.19 54.61,190.51 52.07,193.05 IC40.1 | 83.19,174.64 85.09,176.54 85.09,179.08 81.92,179.08 79.38,176.54 78.11,176.54 77.47,177.18 77.47,179.08 62.23,179.08 61.59,179.72 61.59,184.16 57.15,184.16 54.61,186.7 | 104.14,184.16 102.87,184.16 100.97,186.07 100.97,189.88 99.69,189.88 IC56.19 | 104.14,184.16 108.58,184.16 108.58,174.64 107.95,174 104.78,174 104.78,172.1 IC47.10 | 104.14,184.16 104.14,192.42 104.78,192.42 105.41,193.05 IC47.1 107.95,193.05 109.22,194.32 110.49,194.32 v111.76,193.05 | IC49.10 167.64,165.11 SV4.26 | SV4.26 SV4.25 | v143.51,182.89 145.41,182.89 145.41,172.1 IC48.10 | IC47.19 115.57,190.51 116.84,191.78 131.44,191.78 v136.53,186.7 141.6,191.78 144.78,191.78 146.05,193.05 IC48.1 151.13,193.05 153.67,190.51 IC48.19 | SV4.26 192.41,161.3 202.56,171.46 202.56,194.96 200.66,194.96 198.75,196.86 171.45,196.86 168.28,193.69 168.28,191.15 169.54,191.15 IC49.19 | 60.33,189.24 v87.63,189.24
  Bottom 0.254: v40.01,184.8 38.1,184.8 38.1,172.73 IC33.10 | IC33.19 45.72,193.05 IC40.1 | IC56.19 95.25,190.51 92.71,193.05 IC56.1 v87.63,189.24 | IC49.19 166.37,190.51 163.83,193.05 IC49.1 161.29,193.05 160.02,191.78 157.48,191.78 156.21,190.51 IC48.19 | v143.51,182.89 142.24,184.16 139.06,184.16 v136.53,186.7 | v111.76,193.05 IC47.19
N$42
  Top 0.254: RN5.2 F.3.A
N$43
  Top 0.254: RN5.3 11.43,190.51 12.7,191.78 19.68,191.78 20.95,193.05 F.2.A
N$44
  Top 0.254: RN5.4 11.43,187.97 14.61,191.15 25.4,191.15 27.3,193.05 F.1.A
N$45
  Top 0.254: RN6.2 DEA8.A
N$46
  Top 0.254: RN8.2 DEA2.A
N$47
  Top 0.254: RN8.3 176.53,190.51 177.8,191.78 186.06,191.78 187.32,193.05 DEA1.A
N$48
  Top 0.254: RN7.2 DEA5.A
N$49
  Bottom 0.254: RN7.3 120.65,190.51 121.28,191.15 129.54,191.15 131.44,193.05 DEA4.A
N$50
  Bottom 0.254: RN7.4 120.65,187.97 123.19,190.51 136.53,190.51 139.06,193.05 DEA3.A
N$51
  Top 0.254: RN8.4 176.53,187.97 179.71,191.15 186.69,191.15 187.32,191.78 193.68,191.78 194.94,193.05 DEA0.A
N$52
  Top 0.254: RN8.5 DMA09.A
N$85
  Top 0.254: RN8.6 176.53,182.89 177.16,183.53 185.42,183.53 187.32,185.43 DMA10.A
N$86
  Top 0.254: RN5.5 DMA00.A
N$87
  Top 0.254: RN5.6 11.43,182.89 12.7,184.16 19.68,184.16 20.95,185.43 DMA01.A
N$88
  Top 0.254: RN5.7 11.43,180.35 14.61,183.53 25.4,183.53 27.3,185.43 DMA02.A
N$89
  Bottom 0.254: RN6.3 64.77,190.51 65.41,191.15 73.66,191.15 75.56,193.05 DEA7.A
N$90
  Bottom 0.254: RN6.4 64.77,187.97 67.31,190.51 76.83,190.51 78.11,191.78 80.01,191.78 81.28,193.05 DEA6.A
N$91
  Top 0.254: DMA03.A RN6.5
N$92
  Top 0.254: RN7.6 120.65,182.89 121.28,183.53 127.64,183.53 129.54,185.43 DMA07.A
N$93
  Top 0.254: RN7.5 DMA06.A
N$94  (via drill 0.61)
  Top 0.254: v129.54,184.16 128.27,182.89 123.19,182.89 120.65,180.35 RN7.7
  Bottom 0.254: v129.54,184.16 129.54,189.88 137.16,189.88 139.7,187.34 DMA08.A
N$95
  Bottom 0.254: RN8.7 176.53,180.35 179.71,183.53 192.41,183.53 194.31,185.43 DMA11.A
N$96
  Top 0.254: RN8.8 DMB09.A
N$97
  Top 0.254: RN12.6 176.53,175.27 177.16,175.91 185.42,175.91 187.32,177.81 DMB10.A
N$98
  Top 0.254: RN9.2 11.43,165.11 14.61,168.29 25.4,168.29 27.3,170.19 PIE.A
N$99
  Top 0.254: RN9.3 11.43,167.65 12.7,168.92 19.68,168.92 20.95,170.19 EIE.A
N$100
  Top 0.254: RN9.4 CIE.A
N$101
  Top 0.254: RN6.6 64.77,182.89 66.04,184.16 74.3,184.16 75.56,185.43 DMA04.A
N$102
  Top 0.254: RN6.7 64.77,180.35 67.94,183.53 81.28,183.53 83.19,185.43 DMA05.A
N$103
  Top 0.254: RN6.8 DMB03.A
N$104
  Bottom 0.254: RN7.8 DMB06.A
N$105
  Bottom 0.254: RN11.6 120.65,175.27 121.28,175.91 129.54,175.91 131.44,177.81 DMB07.A
N$106
  Bottom 0.254: RN11.5 120.65,172.73 123.19,175.27 133.99,175.27 136.53,177.81 DMB08.A
N$107  (via drill 0.61)
  Top 0.254: v186.06,174 188.59,176.54 193.68,176.54 194.94,177.81 DMB11.A
  Bottom 0.254: v186.06,174 177.8,174 176.53,172.73 RN12.5
N$108
  Top 0.254: RN12.4 WCO.A
N$109
  Top 0.254: RN12.3 176.53,167.65 177.8,168.92 186.06,168.92 187.32,170.19 PER.A
N$110
  Top 0.254: RN9.5 11.43,172.73 14.61,175.91 25.4,175.91 27.3,177.81 DMB02.A
N$111
  Top 0.254: RN9.6 11.43,175.27 12.7,176.54 19.68,176.54 20.95,177.81 DMB01.A
N$112
  Top 0.254: RN5.8 DMB00.A
N$113
  Top 0.254: RN10.4 DRE.A
N$114
  Bottom 0.254: RN10.3 64.77,167.65 65.41,168.29 73.66,168.29 75.56,170.19 R/W.A
N$115
  Bottom 0.254: RN10.2 64.77,165.11 67.31,167.65 78.11,167.65 80.64,170.19 DBR.A
N$116
  Top 0.254: RN11.4 DRL.A
N$117
  Top 0.254: RN11.3 120.65,167.65 121.28,168.29 129.54,168.29 131.44,170.19 WLS.A
N$118
  Bottom 0.254: RN11.2 120.65,165.11 121.28,164.48 125.73,164.48 127.64,162.57 131.44,162.57 139.06,170.19 NXD.A
N$119
  Top 0.254: RN12.2 176.53,165.11 179.71,168.29 193.04,168.29 194.94,170.19 DCF.A
N$120  (via drill 0.61)
  Top 0.254: v160.66,174 152.4,174 149.86,171.46 148.59,172.73 IC48.9 | v167.64,182.89 168.91,184.16 180.97,184.16 182.25,185.43 DMA09.K
  Bottom 0.254: v160.66,174 160.66,179.08 163.83,179.08 v167.64,182.89
N$121
  Top 0.254: IC48.7 148.59,177.81 149.86,176.54 180.97,176.54 182.25,177.81 DMB09.K
N$122
  Bottom 0.254: F.3.K 18.41,193.05 19.68,194.32 36.83,194.32 IC33.18
N$123
  Top 0.254: DMA00.K 18.41,185.43 19.68,186.7 36.83,186.7 40.64,182.89 IC33.16
N$124
  Top 0.254: CIE.K 18.41,170.19 19.68,171.46 40.64,171.46 41.91,172.73 IC33.12
N$125
  Top 0.254: DMB00.K 18.41,177.81 19.68,179.08 36.83,179.08 38.1,177.81 IC33.14
N$126
  Bottom 0.254: DMA01.K 24.13,179.08 23.5,179.08 22.86,178.45 22.86,176.54 33.02,176.54 34.29,177.81 IC33.7
N$127
  Bottom 0.254: IC33.9 37.47,174.64 37.47,189.24 28.57,189.24 24.77,193.05 F.2.K
N$128
  Bottom 0.254: DMB01.K 24.77,177.81 29.84,182.89 IC33.5
N$129
  Bottom 0.254: EIE.K 24.13,170.83 19.68,175.27 19.68,187.97 IC33.3
N$132
  Top 0.254: F.1.K 30.48,192.42 33.66,189.24 55.88,189.24 57.15,187.97 IC40.18
N$133
  Top 0.254: DMA02.K 30.48,184.8 33.66,181.62 46.99,181.62 49.53,184.16 55.88,184.16 57.15,182.89 IC40.16
N$134
  Top 0.254: DMB02.K 31.11,177.81 32.38,176.54 55.88,176.54 57.15,177.81 IC40.14
N$135
  Top 0.254: PIE.K 31.11,170.19 32.38,168.92 39.37,168.92 41.91,171.46 45.09,171.46 47.62,174 55.88,174 57.15,172.73 IC40.12
N$136
  Top 0.254: DMB03.K 70.48,177.81 69.22,176.54 62.23,176.54 60.96,175.27 59.69,176.54 60.33,177.18 60.33,179.08 55.88,179.08 52.07,182.89 IC40.5
N$137
  Bottom 0.254: IC40.7 57.15,184.16 69.22,184.16 70.48,185.43 DMA03.K
N$138  (via drill 0.61)
  Top 0.254: v80.64,191.15 80.01,191.78 73.03,191.78 71.75,193.05 DEA8.K
  Bottom 0.254: v80.64,191.15 78.74,191.15 66.67,179.08 57.15,179.08 IC40.9
N$139
  Bottom 0.254: IC40.3 52.07,187.97 55.88,191.78 65.41,191.78 67.94,194.32 76.83,194.32 78.11,193.05 DEA7.K
N$140  (via drill 0.61)
  Top 0.254: DMA04.K v81.92,185.43
  Bottom 0.254: v81.92,185.43 83.19,186.7 96.52,186.7 97.79,187.97 IC56.18
N$141  (via drill 0.61)
  Top 0.254: v95.25,181.62 88.9,181.62 88.27,180.99 82.55,180.99 79.38,177.81 DMB04.K
  Bottom 0.254: v95.25,181.62 96.52,182.89 IC56.16
N$142  (via drill 0.61)
  Top 0.254: v86.36,172.73 87.63,174 95.25,174 IC56.14
  Bottom 0.254: v86.36,172.73 84.45,172.73 82.55,170.83 80.01,170.83 79.38,170.19 R/W.K
N$143
  Top 0.254: DMB05.K IC56.7
N$144  (via drill 0.61)
  Top 0.254: v49.53,196.86 69.85,196.86 69.85,192.42 72.39,189.88 86.36,189.88 DEA6.K | v26.67,168.29 29.84,165.11 v58.42,165.11 | v77.47,172.1 79.38,174 82.55,174 v83.19,173.37 | v86.36,174 88.9,176.54 v96.52,176.54
  Bottom 0.254: v49.53,196.86 47.62,194.96 17.78,194.96 16.51,193.69 16.51,168.29 v26.67,168.29 | v58.42,165.11 62.23,168.92 73.03,168.92 76.2,172.1 v77.47,172.1 | v83.19,173.37 83.82,174 v86.36,174 | v96.52,176.54 100.33,176.54 100.97,175.91 100.97,173.37 99.69,173.37 IC56.12
N$145
  Bottom 0.254: DBR.K 86.36,170.83 87.63,172.1 87.63,178.45 87,179.08 87,184.16 87.63,184.16 88.27,184.8 89.53,184.8 IC56.5
N$146
  Top 0.254: IC47.16 115.57,182.89 116.84,184.16 125.09,184.16 126.36,185.43 DMA06.K
N$147  (via drill 0.61)
  Top 0.254: v131.44,182.26 128.91,179.72 124.46,179.72 121.28,176.54 118.11,176.54 IC47.12 | v137.16,188.61 137.16,192.42 134.62,192.42 DEA4.K
  Bottom 0.254: v131.44,182.26 131.44,184.16 130.81,184.8 130.81,188.61 v137.16,188.61
N$148
  Bottom 0.254: IC47.7 107.95,177.81 109.22,179.08 132.72,179.08 133.99,177.81 DMB07.K
N$149
  Bottom 0.254: IC47.18 118.11,191.78 125.09,191.78 126.36,193.05 DEA5.K
N$150
  Top 0.254: IC47.9 107.95,172.73 111.76,176.54 115.57,176.54 118.11,179.08 121.92,179.08 125.09,182.26 130.18,182.26 132.08,184.16 132.72,184.16 133.99,185.43 DMA07.K
N$151
  Bottom 0.254: WLS.K 134.62,174.64 136.53,176.54 140.34,176.54 140.97,177.18 140.97,179.72 127.64,179.72 123.19,184.16 109.22,184.16 107.95,182.89 IC47.5
N$152
  Bottom 0.254: IC47.14 115.57,177.81 116.84,176.54 125.09,176.54 126.36,177.81 DMB06.K
N$153
  Bottom 0.254: IC47.3 109.22,190.51 109.22,191.78 111.76,194.32 140.34,194.32 141.6,193.05 DEA3.K
N$154
  Bottom 0.254: DMA08.K 142.88,185.43 144.15,186.7 152.4,186.7 153.67,187.97 IC48.18
N$155
  Bottom 0.254: DMB08.K 142.24,178.45 145.41,181.62 152.4,181.62 153.67,182.89 IC48.16
N$156
  Bottom 0.254: NXD.K 142.24,170.83 145.41,174 149.86,174 153.67,177.81 IC48.14
N$157  (via drill 0.61)
  Top 0.254: v165.1,170.19 v166.37,168.92 | v157.48,179.08 v160.02,181.62 | v152.4,179.08 148.59,182.89 IC48.5
  Bottom 0.254: v166.37,168.92 180.97,168.92 182.25,170.19 WCO.K | v165.1,170.19 163.83,171.46 161.29,171.46 159.38,173.37 159.38,181.62 v160.02,181.62 | v152.4,179.08 v157.48,179.08
N$158
  Top 0.254: PER.K 189.87,170.19 188.59,171.46 172.72,171.46 171.45,172.73 IC49.12
N$159
  Top 0.254: IC49.14 171.45,177.81 172.72,179.08 188.59,179.08 189.87,177.81 DMB10.K
N$160  (via drill 0.61)
  Top 0.254: v172.72,170.19 171.45,171.46 157.48,171.46 156.21,172.73 IC48.12 | v187.32,174 187.96,174.64 196.85,174.64 199.39,177.18 199.39,186.7 v193.04,186.7
  Bottom 0.254: v172.72,170.19 173.99,171.46 184.78,171.46 v187.32,174 | v193.04,186.7 190.5,189.24 187.32,189.24 183.51,193.05 DEA2.K
N$161
  Bottom 0.254: IC49.16 171.45,182.89 172.72,184.16 188.59,184.16 189.87,185.43 DMA10.K
N$162  (via drill 0.61)
  Top 0.254: v187.32,190.51 183.51,186.7 172.72,186.7 171.45,187.97 IC49.18
  Bottom 0.254: v187.32,190.51 189.87,193.05 DEA1.K
N$163
  Top 0.254: IC48.15 IC48.3
N$164
  Bottom 0.254: IC49.7 163.83,177.81 165.1,179.08 178.44,179.08 182.25,182.89 193.04,182.89 194.31,184.16 196.22,184.16 197.49,185.43 DMA11.K
N$165
  Bottom 0.254: IC49.9 163.83,172.73 167.64,176.54 177.16,176.54 182.25,181.62 187.96,181.62 188.59,182.26 193.68,182.26 194.94,183.53 198.12,183.53 199.39,184.8 199.39,192.42 198.12,192.42 DEA0.K
N$166
  Top 0.254: IC49.5 160.66,180.99 160.66,179.08 171.45,179.08 173.99,181.62 186.69,181.62 188.59,179.72 195.58,179.72 197.49,177.81 DMB11.K
N$167  (via drill 0.61)
  Top 0.254: v201.29,191.78 198.75,194.32 173.35,194.32 173.35,191.15 171.45,189.24 168.91,189.24 167.64,190.51 165.1,190.51 IC49.3
  Bottom 0.254: v201.29,191.78 201.29,170.83 198.12,170.83 DCF.K
N$169
  Top 0.254: PAD10.1 DRE.K
N$170
  Bottom 0.254: PAD11.1 DRL.K
N$171  (via drill 0.61)
  Top 0.254: v85.72,179.72 86.36,179.08 v88.27,179.08
  Bottom 0.254: v85.72,179.72 86.36,179.72 DMA05.K | v88.27,179.08 88.27,173.37 90.81,173.37 IC56.9
N$172
  Top 0.254: RN10.6 64.77,175.27 65.41,175.91 73.66,175.91 75.56,177.81 DMB04.A
N$173
  Top 0.254: RN10.5 64.77,172.73 67.31,175.27 80.64,175.27 83.19,177.81 DMB05.A
N$175
  Top 0.254: IC56.15 IC56.3
NXD  (via drill 0.61)
  Top 0.254: v135.89,174.64 134.62,173.37 v122.56,173.37 | v112.39,171.46 109.22,168.29 v108.58,168.29
  Bottom 0.254: v135.89,174.64 140.97,174.64 143.51,177.18 144.15,177.18 IC48.6 | v122.56,173.37 120.65,171.46 v112.39,171.46 | v108.58,168.29 102.87,162.57 102.87,159.4 101.6,159.4 SV3.17
PER  (via drill 0.61)
  Top 0.254: v152.4,172.73 152.4,172.1 153.03,171.46 153.03,164.48 152.4,164.48 151.76,163.84 v135.25,163.84 | v128.27,161.3 127.64,160.67 116.2,160.67 113.03,157.49 108.58,157.49 107.31,158.76 SV3.21 | v157.48,175.27 IC49.8
  Bottom 0.254: v157.48,175.27 156.21,174 153.67,174 v152.4,172.73 | v135.25,163.84 132.72,161.3 v128.27,161.3
PIE
  Bottom 0.254: IC40.8 48.9,173.37 48.9,157.49 84.45,157.49 85.72,158.76 SV3.5
VCC  (via drill 0.61)
  Top 0.508: v102.23,195.59 101.6,194.96 100.97,194.96 IC56.20 | IC47.20 115.57,193.05 118.11,195.59 RN7.1 153.67,195.59 155.57,193.69 IC48.20 | v197.49,187.97 200.03,187.97 200.03,170.19 197.49,167.65 181.61,167.65 176.53,162.57 RN12.1 | IC49.20 172.72,195.59 RN8.1 | IC40.20 59.69,193.05 62.23,195.59 RN6.1 | RN11.1 113.67,162.57 112.39,161.3 SV3.26 SV3.25 111.12,158.76 109.86,160.03 106.05,160.03 105.41,159.4 105.41,156.86 86.36,156.86 85.09,158.13 85.09,160.03 67.31,160.03 64.77,162.57 RN10.1 RN9.1 8.26,164.48 8.26,195.59 RN5.1 39.37,195.59 41.91,193.05 IC33.20 42.55,193.69 47.62,198.77 89.53,198.77 89.53,197.5 v93.98,193.05
  Bottom 0.508: v102.23,195.59 RN7.1 | IC48.20 156.21,193.05 157.48,194.32 167.64,194.32 168.91,193.05 IC49.20 | v197.49,187.97 189.87,195.59 RN8.1 | IC33.20 44.45,193.05 45.72,194.32 55.88,194.32 57.15,195.59 RN6.1 | v93.98,193.05 94.61,193.69 97.16,193.69 97.79,193.05 IC56.20
WLS  (via drill 0.61)
  Top 0.254: v109.22,193.05 v111.12,191.15 | v95.89,196.86 93.34,199.4 10.79,199.4 7.62,196.23 7.62,158.13 v46.99,158.13 | v109.22,185.43 IC47.15
  Bottom 0.254: v109.22,185.43 109.22,186.7 111.12,188.61 v111.12,191.15 | v109.22,193.05 107.31,194.96 102.87,194.96 102.23,194.32 101.6,194.32 99.06,196.86 v95.89,196.86 | v46.99,158.13 48.26,156.86 96.52,156.86 98.42,158.76 SV3.15
WRITING  (via drill 0.61)
  Top 0.254: v85.09,182.26 88.27,182.26 90.17,184.16 93.98,184.16 96.52,181.62 95.25,180.35 IC56.6 | v81.92,172.1 81.92,168.29 v90.81,168.29
  Bottom 0.254: v85.09,182.26 81.92,179.08 v81.92,172.1 | v90.81,168.29 90.81,163.21 91.44,163.21 92.71,161.94 92.71,159.4 91.44,159.4 SV3.9

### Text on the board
Bottom: RS08 | VRS | RF08 Debug | VRS | RS08 | VRS | RF08 | VRS
tPlace: RF08 | VRS
tValues: VRS | RF08 Debug | RS08 | VRS | RS08 | VRS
